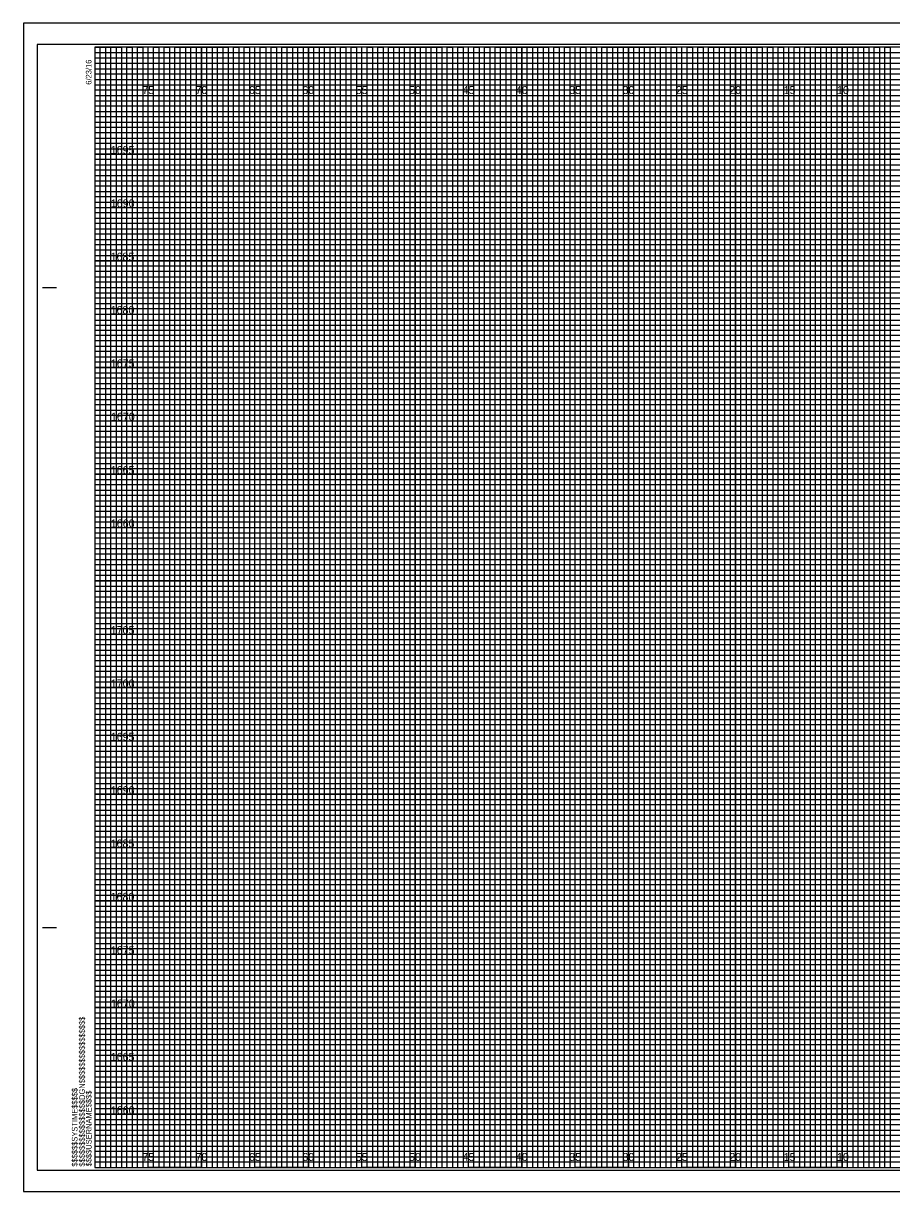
# Model space of a CAD drawing. Extents: x -73 to 95, y 6 to 446.
# Drawn here: x -73.1 to 8.2, y 6.1 to 115.6 of the extents above; entities that cross this region are included whole.
import ezdxf

# ---------------------------------------------------------------- set-up
doc = ezdxf.new("R2010")
doc.units = 0
for name, color, linetype in [('Exist CMT Alignment Centerline', 7, 'Continuous'), ('Prop Horizontal Alignment', 7, 'Continuous'), ('Prop XS DDE', 7, 'Continuous'), ('Raster_Level_0', 7, 'Continuous'), ('Sheet Cross Section CELL', 7, 'Continuous'), ('Sheet Cross Section Grid Minor 1 CELL', 7, 'Continuous'), ('Sheet Cross Section Grid Minor 2 CELL', 7, 'Continuous'), ('Sheet Cutting Line CELL', 7, 'Continuous'), ('Sheet DOT Grid CELL', 7, 'Continuous'), ('Sheet Plot Border Inside CELL', 7, 'Continuous'), ('Sheet Plot Border Outside CELL', 7, 'Continuous')]:
    doc.layers.add(name, color=color, linetype=linetype)

msp = doc.modelspace()

# ---------------------------------------------------------------- linework, layer by layer
at = {"layer": 'Exist CMT Alignment Centerline'}
for p, q in [((-61.4, 113.4), (-66.4, 113.4)), ((-61.4, 8.4), (-61.4, 113.4)), ((-51.4, 113.4), (-56.4, 113.4)), ((-56.4, 113.4), (-56.4, 8.4)), ((-51.4, 8.4), (-51.4, 113.4)), ((-41.4, 113.4), (-46.4, 113.4)), ((-46.4, 113.4), (-46.4, 8.4)), ((-41.4, 8.4), (-41.4, 113.4)), ((-31.4, 113.4), (-36.4, 113.4)), ((-36.4, 113.4), (-36.4, 8.4)), ((-31.4, 8.4), (-31.4, 113.4)), ((-21.4, 113.4), (-26.4, 113.4)), ((-26.4, 113.4), (-26.4, 8.4)), ((-21.4, 8.4), (-21.4, 113.4)), ((-11.4, 113.4), (-16.4, 113.4)), ((-16.4, 113.4), (-16.4, 8.4)), ((-11.4, 8.4), (-11.4, 113.4)), ((-1.4, 113.4), (-6.4, 113.4)), ((-6.4, 113.4), (-6.4, 8.4)), ((-1.4, 8.4), (-1.4, 113.4)), ((8.6, 113.4), (3.6, 113.4)), ((3.6, 113.4), (3.6, 8.4)), ((-56.4, 8.4), (-61.4, 8.4)), ((-46.4, 8.4), (-51.4, 8.4)), ((-36.4, 8.4), (-41.4, 8.4)), ((-26.4, 8.4), (-31.4, 8.4)), ((-16.4, 8.4), (-21.4, 8.4)), ((-6.4, 8.4), (-11.4, 8.4)), ((3.6, 8.4), (-1.4, 8.4))]:
    msp.add_line(p, q, dxfattribs=at)
for points in [[(-66.4, 108.4), (93.6, 108.4), (93.6, 103.4), (-66.4, 103.4)], [(-66.4, 98.4), (93.6, 98.4), (93.6, 93.4), (-66.4, 93.4)], [(-66.4, 88.4), (93.6, 88.4), (93.6, 83.4), (-66.4, 83.4)], [(-66.4, 78.4), (93.6, 78.4), (93.6, 73.4), (-66.4, 73.4)], [(-66.4, 68.4), (93.6, 68.4), (93.6, 63.4), (-66.4, 63.4)], [(-66.4, 58.4), (93.6, 58.4), (93.6, 53.4), (-66.4, 53.4)], [(-66.4, 48.4), (93.6, 48.4), (93.6, 43.4), (-66.4, 43.4)], [(-66.4, 38.4), (93.6, 38.4), (93.6, 33.4), (-66.4, 33.4)], [(-66.4, 28.4), (93.6, 28.4), (93.6, 23.4), (-66.4, 23.4)], [(-66.4, 18.4), (93.6, 18.4), (93.6, 13.4), (-66.4, 13.4)]]:
    msp.add_lwpolyline(points, dxfattribs=at)
at = {"layer": 'Prop XS DDE'}
for points in [[(-66.4, 113.4), (-63.9, 113.4), (-63.9, 8.4), (-58.9, 8.4), (-58.9, 113.4), (-53.9, 113.4), (-53.9, 8.4), (-48.9, 8.4), (-48.9, 113.4), (-43.9, 113.4), (-43.9, 8.4), (-38.9, 8.4), (-38.9, 113.4), (-33.9, 113.4), (-33.9, 8.4), (-28.9, 8.4), (-28.9, 113.4), (-23.9, 113.4), (-23.9, 8.4), (-18.9, 8.4), (-18.9, 113.4), (-13.9, 113.4), (-13.9, 8.4), (-8.9, 8.4), (-8.9, 113.4), (-3.9, 113.4), (-3.9, 8.4), (1.1, 8.4), (1.1, 113.4), (6.1, 113.4), (6.1, 8.4), (11.1, 8.4)], [(-66.4, 110.9), (71.1, 110.9)], [(-66.4, 100.9), (93.6, 100.9), (93.6, 105.9), (-66.4, 105.9)], [(-66.4, 90.9), (93.6, 90.9), (93.6, 95.9), (-66.4, 95.9)], [(-66.4, 80.9), (93.6, 80.9), (93.6, 85.9), (-66.4, 85.9)], [(-66.4, 70.9), (93.6, 70.9), (93.6, 75.9), (-66.4, 75.9)], [(-66.4, 60.9), (93.6, 60.9), (93.6, 65.9), (-66.4, 65.9)], [(-66.4, 50.9), (93.6, 50.9), (93.6, 55.9), (-66.4, 55.9)], [(-66.4, 40.9), (93.6, 40.9), (93.6, 45.9), (-66.4, 45.9)], [(-66.4, 30.9), (93.6, 30.9), (93.6, 35.9), (-66.4, 35.9)], [(-66.4, 20.9), (93.6, 20.9), (93.6, 25.9), (-66.4, 25.9)], [(-66.4, 10.9), (93.6, 10.9), (93.6, 15.9), (-66.4, 15.9)]]:
    msp.add_lwpolyline(points, dxfattribs=at)
at = {"layer": 'Sheet Cross Section CELL'}
for p, q in [((-71.3, 90.9), (-70.05, 90.9)), ((-71.25, 90.9), (-70, 90.9)), ((-71.3, 30.9), (-70.05, 30.9)), ((-71.25, 30.9), (-70, 30.9)), ((-66.4, 8.4), (-66.4, 8.4)), ((-66.4, 8.4), (-66.4, 8.4)), ((-66.4, 8.4), (-66.4, 8.4)), ((-66.4, 8.4), (-66.4, 8.4)), ((-66.4, 8.4), (-66.4, 8.4)), ((-66.4, 8.4), (-66.4, 8.4)), ((-66.4, 8.4), (-66.4, 8.4))]:
    msp.add_line(p, q, dxfattribs=at)
msp.add_lwpolyline([(93.6, 113.4), (-66.4, 113.4), (-66.4, 8.4), (93.6, 8.4)], close=True, dxfattribs=at)
at = {"layer": 'Sheet Cross Section Grid Minor 1 CELL'}
for p, q in [((-66.4, 112.9), (63.6, 112.9)), ((63.6, 112.39), (-66.4, 112.39)), ((-66.4, 112.39), (-66.4, 111.9)), ((-66.4, 111.9), (63.6, 111.9)), ((63.6, 111.34), (-66.4, 111.34)), ((-66.4, 111.34), (-66.4, 110.4)), ((-66.4, 110.4), (93.6, 110.4))]:
    msp.add_line(p, q, dxfattribs=at)
for points in [[(-66.4, 109.9), (68.6, 109.9), (93.6, 109.9), (93.6, 109.4), (-66.4, 109.4)], [(-66.4, 108.9), (93.6, 108.9), (93.6, 107.9), (-66.4, 107.9)], [(-66.4, 107.4), (93.6, 107.4), (93.6, 106.9), (-66.4, 106.89)], [(-66.4, 106.4), (93.6, 106.4), (93.6, 105.4), (-66.4, 105.4)], [(-66.4, 104.9), (93.6, 104.9), (93.6, 104.4), (-66.4, 104.4)], [(-66.4, 103.9), (93.6, 103.9), (93.6, 102.9), (-66.4, 102.9)], [(-66.4, 102.4), (93.6, 102.4), (93.6, 101.9), (-66.4, 101.9)], [(-66.4, 101.4), (93.6, 101.4), (93.6, 100.4), (-66.4, 100.4)], [(-66.4, 99.9), (93.6, 99.9), (93.6, 99.4), (-66.4, 99.4)], [(-66.4, 98.9), (93.6, 98.9), (93.6, 97.9), (-66.4, 97.9)], [(-66.4, 97.4), (93.6, 97.4), (93.6, 96.9), (-66.4, 96.9)], [(-66.4, 96.4), (93.6, 96.4), (93.6, 95.37), (93.6, 94.9), (93.6, 94.4), (-66.4, 94.4)], [(-66.4, 95.4), (93.6, 95.4), (93.6, 94.9), (-66.4, 94.9)], [(-66.4, 93.9), (93.6, 93.9), (93.6, 92.9), (-66.4, 92.91)], [(-66.4, 92.91), (93.6, 92.9), (93.6, 92.4), (-66.4, 92.4)], [(-66.4, 91.9), (93.6, 91.9), (93.6, 91.4), (-66.4, 91.4)], [(-66.4, 90.4), (93.6, 90.4), (93.6, 89.9), (-66.4, 89.9)], [(-66.4, 89.4), (93.6, 89.4), (93.6, 88.9), (-66.4, 88.9)], [(-66.43, 87.84), (93.6, 87.84), (93.6, 87.34), (-66.43, 87.34)], [(-66.4, 86.9), (93.6, 86.9), (93.6, 86.4), (-66.4, 86.4)], [(-66.4, 85.4), (93.6, 85.4), (93.6, 84.9), (-66.4, 84.9)], [(-66.4, 84.4), (93.6, 84.4), (93.6, 83.9), (-66.4, 83.9)], [(-66.4, 82.9), (93.6, 82.9), (93.6, 82.4), (-66.4, 82.4)], [(-66.4, 81.9), (93.6, 81.9), (93.6, 81.4), (-66.4, 81.4)], [(-66.4, 80.4), (93.6, 80.4), (93.6, 79.9), (-66.4, 79.9)], [(-66.4, 79.4), (93.6, 79.4), (93.6, 78.9), (-66.4, 78.9)], [(-66.4, 77.9), (93.6, 77.9), (93.6, 77.39), (-66.4, 77.4)], [(-66.4, 76.9), (93.6, 76.9), (93.6, 76.4), (-66.4, 76.4)], [(-66.4, 75.4), (93.6, 75.4), (93.6, 74.9), (-66.4, 74.9)], [(-66.4, 74.4), (93.6, 74.4), (93.6, 73.9), (-66.4, 73.9)], [(-66.4, 72.9), (93.6, 72.9), (93.6, 72.4), (-66.4, 72.4)], [(-66.4, 71.9), (93.6, 71.9), (93.6, 71.4), (-66.4, 71.4)], [(-66.4, 70.4), (93.6, 70.4), (93.6, 69.9), (-66.4, 69.9)], [(-66.4, 69.4), (93.6, 69.4), (93.6, 68.9), (-66.4, 68.9)], [(-66.4, 67.9), (93.6, 67.9), (93.6, 67.4), (-66.4, 67.4)], [(-66.4, 66.89), (93.64, 66.85), (93.6, 66.4), (-66.4, 66.4)], [(-66.4, 65.4), (93.6, 65.4), (93.6, 64.9), (-66.4, 64.9)], [(-66.4, 64.4), (93.6, 64.4), (93.6, 63.9), (-66.4, 63.9)], [(-66.4, 62.9), (93.6, 62.9), (93.6, 62.4), (-66.4, 62.4)], [(-66.4, 61.9), (93.6, 61.9), (93.6, 61.4), (-66.4, 61.4)], [(-66.4, 60.4), (93.6, 60.4), (93.6, 59.9), (-66.4, 59.9)], [(-66.4, 59.4), (93.6, 59.4), (93.6, 58.9), (-66.4, 58.9)], [(-66.4, 57.9), (93.6, 57.9), (93.6, 57.4), (-66.4, 57.4)], [(-66.4, 56.9), (93.6, 56.9), (93.6, 56.4), (-66.4, 56.4)], [(-66.4, 55.4), (93.6, 55.4), (93.6, 54.9), (-66.4, 54.9)], [(-66.4, 54.4), (93.6, 54.4), (93.6, 53.9), (-66.4, 53.9)], [(-66.4, 52.9), (93.6, 52.9), (93.6, 52.4), (-66.4, 52.4)], [(-66.4, 51.9), (93.6, 51.9), (93.6, 51.4), (-66.4, 51.4)], [(-66.4, 50.4), (93.6, 50.4), (93.6, 49.9), (-66.4, 49.9)], [(-66.4, 49.4), (93.6, 49.4), (93.6, 48.9), (-66.4, 48.9)], [(-66.4, 47.9), (93.6, 47.9), (93.6, 47.39), (-66.4, 47.4)], [(-66.4, 46.9), (93.6, 46.9), (93.6, 46.4), (-66.4, 46.4)], [(-66.4, 45.4), (93.6, 45.4), (93.6, 44.9), (-66.4, 44.9)], [(-66.4, 44.4), (93.6, 44.4), (93.6, 43.9), (-66.4, 43.9)], [(-66.4, 42.9), (93.6, 42.9), (93.6, 42.4), (-66.4, 42.4)], [(-66.4, 41.9), (93.6, 41.9), (93.6, 41.4), (-66.4, 41.4)], [(-66.4, 40.4), (93.6, 40.4), (93.6, 39.9), (-66.4, 39.9)], [(-66.4, 39.4), (93.6, 39.4), (93.6, 38.9), (-66.4, 38.9)], [(-66.4, 37.9), (93.6, 37.9), (93.6, 37.4), (-66.4, 37.4)], [(-66.4, 36.89), (93.64, 36.85), (93.6, 36.4), (-66.4, 36.4)], [(-66.4, 35.4), (93.6, 35.4), (93.6, 34.9), (-66.4, 34.9)], [(-66.4, 34.4), (93.6, 34.4), (93.6, 33.9), (-66.4, 33.9)], [(-66.4, 32.9), (93.6, 32.9), (93.6, 32.4), (-66.4, 32.4)], [(-66.4, 31.9), (93.6, 31.9), (93.6, 31.4), (-66.4, 31.4)], [(-66.4, 30.4), (93.6, 30.4), (93.6, 29.9), (-66.4, 29.9)], [(-66.4, 29.4), (93.6, 29.4), (93.6, 28.9), (-66.4, 28.9)], [(-66.4, 27.9), (93.6, 27.9), (93.6, 27.4), (-66.4, 27.4)], [(-66.4, 26.9), (93.6, 26.9), (93.6, 26.4), (-66.4, 26.4)], [(-66.4, 25.4), (93.6, 25.4), (93.6, 24.9), (-66.4, 24.9)], [(-66.4, 24.4), (93.6, 24.4), (93.6, 23.9), (-66.4, 23.9)], [(-66.4, 22.9), (93.6, 22.9), (93.6, 22.4), (-66.4, 22.4)], [(-66.4, 21.9), (93.6, 21.9), (93.6, 21.4), (-66.4, 21.4)], [(-66.4, 20.4), (93.6, 20.4), (93.6, 19.9), (-66.4, 19.9)], [(-66.4, 19.4), (93.6, 19.4), (93.6, 18.9), (-66.4, 18.9)], [(-66.4, 17.9), (93.6, 17.9), (93.6, 17.4), (-66.4, 17.4)], [(-66.4, 16.9), (93.6, 16.9), (93.6, 16.4), (-66.4, 16.4)], [(-66.4, 15.4), (93.6, 15.4), (93.6, 14.9), (-66.4, 14.9)], [(-66.4, 14.4), (93.6, 14.4), (93.6, 13.9), (-66.4, 13.9)], [(-66.4, 12.9), (93.6, 12.9), (93.6, 12.4), (-66.4, 12.4)], [(-66.4, 11.9), (93.6, 11.9), (93.6, 11.4), (-66.4, 11.4)], [(-66.4, 10.4), (93.6, 10.4), (93.6, 9.9), (-66.4, 9.9)], [(-66.4, 9.4), (93.6, 9.4), (93.6, 8.9), (-66.4, 8.9)]]:
    msp.add_lwpolyline(points, dxfattribs=at)
at = {"layer": 'Sheet Cross Section Grid Minor 2 CELL'}
for points in [[(-66.4, 8.4), (-65.9, 8.4), (-65.9, 113.4), (-65.4, 113.4), (-65.4, 8.4)], [(-65.4, 8.4), (-64.9, 8.4), (-64.9, 113.4), (-64.4, 113.4), (-64.4, 8.4)], [(-63.9, 8.4), (-63.4, 8.4), (-63.4, 113.4), (-62.9, 113.4), (-62.9, 8.4)], [(-62.9, 8.4), (-62.4, 8.4), (-62.4, 113.4), (-61.9, 113.4), (-61.9, 8.4)], [(-61.4, 8.4), (-60.9, 8.4), (-60.9, 113.4), (-60.4, 113.4), (-60.4, 8.4)], [(-60.4, 8.4), (-59.9, 8.4), (-59.9, 113.4), (-59.4, 113.4), (-59.4, 8.4)], [(-58.9, 8.4), (-58.4, 8.4), (-58.4, 113.4), (-57.9, 113.4), (-57.9, 8.4)], [(-57.9, 8.4), (-57.4, 8.4), (-57.4, 113.4), (-56.9, 113.4), (-56.9, 8.4)], [(-56.4, 8.4), (-55.9, 8.4), (-55.9, 113.4), (-55.4, 113.4), (-55.4, 8.4)], [(-55.4, 8.4), (-54.9, 8.4), (-54.9, 113.4), (-54.4, 113.4), (-54.4, 8.4)], [(-53.9, 8.4), (-53.4, 8.4), (-53.4, 113.4), (-52.9, 113.4), (-52.9, 8.4)], [(-52.9, 8.4), (-52.4, 8.4), (-52.4, 113.4), (-51.9, 113.4), (-51.9, 8.4)], [(-51.4, 8.4), (-50.9, 8.4), (-50.9, 113.4), (-50.4, 113.4), (-50.4, 8.4)], [(-50.4, 8.4), (-49.9, 8.4), (-49.9, 113.4), (-49.4, 113.4), (-49.4, 8.4)], [(-48.9, 8.4), (-48.4, 8.4), (-48.4, 113.4), (-47.9, 113.4), (-47.9, 8.4)], [(-47.9, 8.4), (-47.4, 8.4), (-47.4, 113.4), (-46.9, 113.4), (-46.9, 8.4)], [(-46.4, 8.4), (-45.9, 8.4), (-45.9, 113.4), (-45.4, 113.4), (-45.4, 8.4)], [(-45.4, 8.4), (-44.9, 8.4), (-44.9, 113.4), (-44.4, 113.4), (-44.4, 8.4)], [(-43.9, 8.4), (-43.4, 8.4), (-43.4, 113.4), (-42.9, 113.4), (-42.9, 8.4)], [(-42.9, 8.4), (-42.4, 8.4), (-42.4, 113.4), (-41.9, 113.4), (-41.9, 8.4)], [(-41.4, 8.4), (-40.9, 8.4), (-40.9, 113.4), (-40.4, 113.4), (-40.4, 8.4)], [(-40.4, 8.4), (-39.9, 8.4), (-39.9, 113.4), (-39.4, 113.4), (-39.4, 8.4)], [(-38.9, 8.4), (-38.4, 8.4), (-38.4, 113.4), (-37.9, 113.4), (-37.9, 8.4)], [(-37.9, 8.4), (-37.4, 8.4), (-37.4, 113.4), (-36.9, 113.4), (-36.9, 8.4)], [(-36.4, 8.4), (-35.9, 8.4), (-35.9, 113.4), (-35.4, 113.4), (-35.4, 8.4)], [(-35.4, 8.4), (-34.9, 8.4), (-34.9, 113.4), (-34.4, 113.4), (-34.4, 8.4)], [(-33.9, 8.4), (-33.4, 8.4), (-33.4, 113.4), (-32.9, 113.4), (-32.9, 8.4)], [(-32.9, 8.4), (-32.4, 8.4), (-32.4, 113.4), (-31.9, 113.4), (-31.9, 8.4)], [(-31.4, 8.4), (-30.9, 8.4), (-30.9, 113.4), (-30.4, 113.4), (-30.4, 8.4)], [(-30.4, 8.4), (-29.9, 8.4), (-29.9, 113.4), (-29.4, 113.4), (-29.4, 8.4)], [(-28.9, 8.4), (-28.4, 8.4), (-28.4, 113.4), (-27.9, 113.4), (-27.9, 8.4)], [(-27.9, 8.4), (-27.4, 8.4), (-27.4, 113.4), (-26.9, 113.4), (-26.9, 8.4)], [(-26.4, 8.4), (-25.9, 8.4), (-25.9, 113.4), (-25.4, 113.4), (-25.4, 8.4)], [(-25.4, 8.4), (-24.9, 8.4), (-24.9, 113.4), (-24.4, 113.4), (-24.4, 8.4)], [(-23.9, 8.4), (-23.4, 8.4), (-23.4, 113.4), (-22.9, 113.4), (-22.9, 8.4)], [(-22.9, 8.4), (-22.4, 8.4), (-22.4, 113.4), (-21.9, 113.4), (-21.9, 8.4)], [(-21.4, 8.4), (-20.9, 8.4), (-20.9, 113.4), (-20.4, 113.4), (-20.4, 8.4)], [(-20.4, 8.4), (-19.9, 8.4), (-19.9, 113.4), (-19.4, 113.4), (-19.4, 8.4)], [(-18.9, 8.4), (-18.4, 8.4), (-18.4, 113.4), (-17.9, 113.4), (-17.9, 8.4)], [(-17.9, 8.4), (-17.4, 8.4), (-17.4, 113.4), (-16.9, 113.4), (-16.9, 8.4)], [(-16.4, 8.4), (-15.9, 8.4), (-15.9, 113.4), (-15.4, 113.4), (-15.4, 8.4)], [(-15.4, 8.4), (-14.9, 8.4), (-14.9, 113.4), (-14.4, 113.4), (-14.4, 8.4)], [(-13.9, 8.4), (-13.4, 8.4), (-13.4, 113.4), (-12.9, 113.4), (-12.9, 8.4)], [(-12.9, 8.4), (-12.4, 8.4), (-12.4, 113.4), (-11.9, 113.4), (-11.9, 8.4)], [(-11.4, 8.4), (-10.9, 8.4), (-10.9, 113.4), (-10.4, 113.4), (-10.4, 8.4)], [(-10.4, 8.4), (-9.9, 8.4), (-9.9, 113.4), (-9.4, 113.4), (-9.4, 8.4)], [(-8.9, 8.4), (-8.4, 8.4), (-8.4, 113.4), (-7.9, 113.4), (-7.9, 8.4)], [(-7.9, 8.4), (-7.4, 8.4), (-7.4, 113.4), (-6.9, 113.4), (-6.9, 8.4)], [(-6.4, 8.4), (-5.9, 8.4), (-5.9, 113.4), (-5.4, 113.4), (-5.4, 8.4)], [(-5.4, 8.4), (-4.9, 8.4), (-4.9, 113.4), (-4.4, 113.4), (-4.4, 8.4)], [(-3.9, 8.4), (-3.4, 8.4), (-3.4, 113.4), (-2.9, 113.4), (-2.9, 8.4)], [(-2.9, 8.4), (-2.4, 8.4), (-2.4, 113.4), (-1.9, 113.4), (-1.9, 8.4)], [(-1.4, 8.4), (-0.9, 8.4), (-0.9, 113.4), (-0.4, 113.4), (-0.4, 8.4)], [(-0.4, 8.4), (0.1, 8.4), (0.1, 113.4), (0.6, 113.4), (0.6, 8.4)], [(1.1, 8.4), (1.6, 8.4), (1.6, 113.4), (2.1, 113.4), (2.1, 8.4)], [(2.1, 8.4), (2.6, 8.4), (2.6, 113.4), (3.1, 113.4), (3.1, 8.4)], [(3.6, 8.4), (4.1, 8.4), (4.1, 113.4), (4.6, 113.4), (4.6, 8.4)], [(4.6, 8.4), (5.1, 8.4), (5.1, 113.4), (5.6, 113.4), (5.6, 8.4)], [(6.1, 8.4), (6.6, 8.4), (6.6, 113.4), (7.1, 113.4), (7.1, 8.4)], [(7.1, 8.4), (7.6, 8.4), (7.6, 113.4), (8.1, 113.4), (8.1, 8.4)]]:
    msp.add_lwpolyline(points, dxfattribs=at)
at = {"layer": 'Sheet Cutting Line CELL'}
for p, q in [((95.25, 115.65), (-73.1, 115.65)), ((-73.1, 115.65), (-73.1, 6.15)), ((-73.1, 6.15), (95.25, 6.15))]:
    msp.add_line(p, q, dxfattribs=at)
at = {"layer": 'Sheet DOT Grid CELL'}
for p, q in [((-61.4, 8.4), (-61.4, 113.4)), ((-56.4, 8.4), (-56.4, 113.4)), ((-51.4, 8.4), (-51.4, 113.4)), ((-46.4, 8.4), (-46.4, 113.4)), ((-41.4, 8.4), (-41.4, 113.4)), ((-36.4, 8.4), (-36.4, 113.4)), ((-31.4, 8.4), (-31.4, 113.4)), ((-26.4, 8.4), (-26.4, 113.4)), ((-21.4, 8.4), (-21.4, 113.4)), ((-16.4, 8.4), (-16.4, 113.4)), ((-11.4, 8.4), (-11.4, 113.4)), ((-6.4, 8.4), (-6.4, 113.4)), ((-1.4, 8.4), (-1.4, 113.4)), ((3.6, 8.4), (3.6, 113.4)), ((-66.4, 108.4), (93.6, 108.4)), ((-66.4, 103.4), (93.6, 103.4)), ((-66.4, 98.4), (93.6, 98.4)), ((-66.4, 93.4), (93.6, 93.4)), ((-66.4, 88.4), (93.6, 88.4)), ((-66.4, 83.4), (93.6, 83.4)), ((-66.4, 78.4), (93.6, 78.4)), ((-66.4, 73.4), (93.6, 73.4)), ((-66.4, 68.4), (93.6, 68.4)), ((-66.4, 63.4), (93.6, 63.4)), ((-66.4, 58.4), (93.6, 58.4)), ((-66.4, 53.4), (93.6, 53.4)), ((-66.4, 48.4), (93.6, 48.4)), ((-66.4, 43.4), (93.6, 43.4)), ((-66.4, 38.4), (93.6, 38.4)), ((-66.4, 33.4), (93.6, 33.4)), ((-66.4, 28.4), (93.6, 28.4)), ((-66.4, 23.4), (93.6, 23.4)), ((-66.4, 18.4), (93.6, 18.4)), ((-66.4, 13.4), (93.6, 13.4))]:
    msp.add_line(p, q, dxfattribs=at)
at = {"layer": 'Sheet Plot Border Inside CELL'}
msp.add_lwpolyline([(-71.8, 8.15), (94.8, 8.15), (94.8, 113.65), (-71.8, 113.65)], close=True, dxfattribs=at)
at = {"layer": 'Sheet Plot Border Outside CELL'}
msp.add_lwpolyline([(-73.1, 6.15), (95.25, 6.15), (95.25, 115.65), (-73.1, 115.65)], close=True, dxfattribs=at)

# ---------------------------------------------------------------- texts
at = {"layer": 'Prop Horizontal Alignment'}
for s, p in [('1695', (-64.92, 103.4)), ('1690', (-64.91, 98.4)), ('1685', (-64.93, 93.4)), ('1680', (-64.93, 88.4)), ('1675', (-64.91, 83.4)), ('1670', (-64.9, 78.4)), ('1665', (-64.92, 73.4)), ('1660', (-64.91, 68.4)), ('1705', (-64.92, 58.4)), ('1700', (-64.91, 53.4)), ('1695', (-64.92, 48.4)), ('1690', (-64.91, 43.4)), ('1685', (-64.93, 38.4)), ('1680', (-64.93, 33.4)), ('1675', (-64.91, 28.4)), ('1670', (-64.9, 23.4)), ('1665', (-64.92, 18.4)), ('1660', (-64.91, 13.4))]:
    msp.add_text(s, height=0.75, dxfattribs=at).set_placement(p)
at = {"layer": 'Raster_Level_0'}
for s, p in [('75', (-61.96, 109.02)), ('70', (-56.97, 109.02)), ('65', (-51.96, 109.02)), ('60', (-46.97, 109.02)), ('55', (-41.96, 109.02)), ('50', (-36.97, 109.02)), ('45', (-31.96, 109.02)), ('40', (-26.97, 109.02)), ('35', (-21.96, 109.02)), ('30', (-16.97, 109.02)), ('25', (-11.96, 109.02)), ('20', (-6.97, 109.02)), ('15', (-1.87, 109.02)), ('10', (3.12, 109.02)), ('75', (-61.96, 9.02)), ('70', (-56.97, 9.02)), ('65', (-51.96, 9.02)), ('60', (-46.97, 9.02)), ('55', (-41.96, 9.02)), ('50', (-36.97, 9.02)), ('45', (-31.96, 9.02)), ('40', (-26.97, 9.02)), ('35', (-21.96, 9.02)), ('30', (-16.97, 9.02)), ('25', (-11.96, 9.02)), ('20', (-6.97, 9.02)), ('15', (-1.87, 9.02)), ('10', (3.12, 9.02))]:
    msp.add_text(s, height=0.75, dxfattribs=at).set_placement(p)
at = {"layer": 'Sheet Cross Section CELL'}
for s, p in [('6/23/16', (-66.72, 109.9)), ('$$$$$$$$$$$$$$$$DGN$$$$$$$$$$$$$$$$', (-67.34, 8.49)), ('$$$$$$SYSTIME$$$$$', (-68.03, 8.49)), ('$$$$USERNAME$$$$', (-66.71, 8.51))]:
    msp.add_text(s, height=0.525, rotation=90, dxfattribs=at).set_placement(p)

doc.saveas('drawing.dxf')
